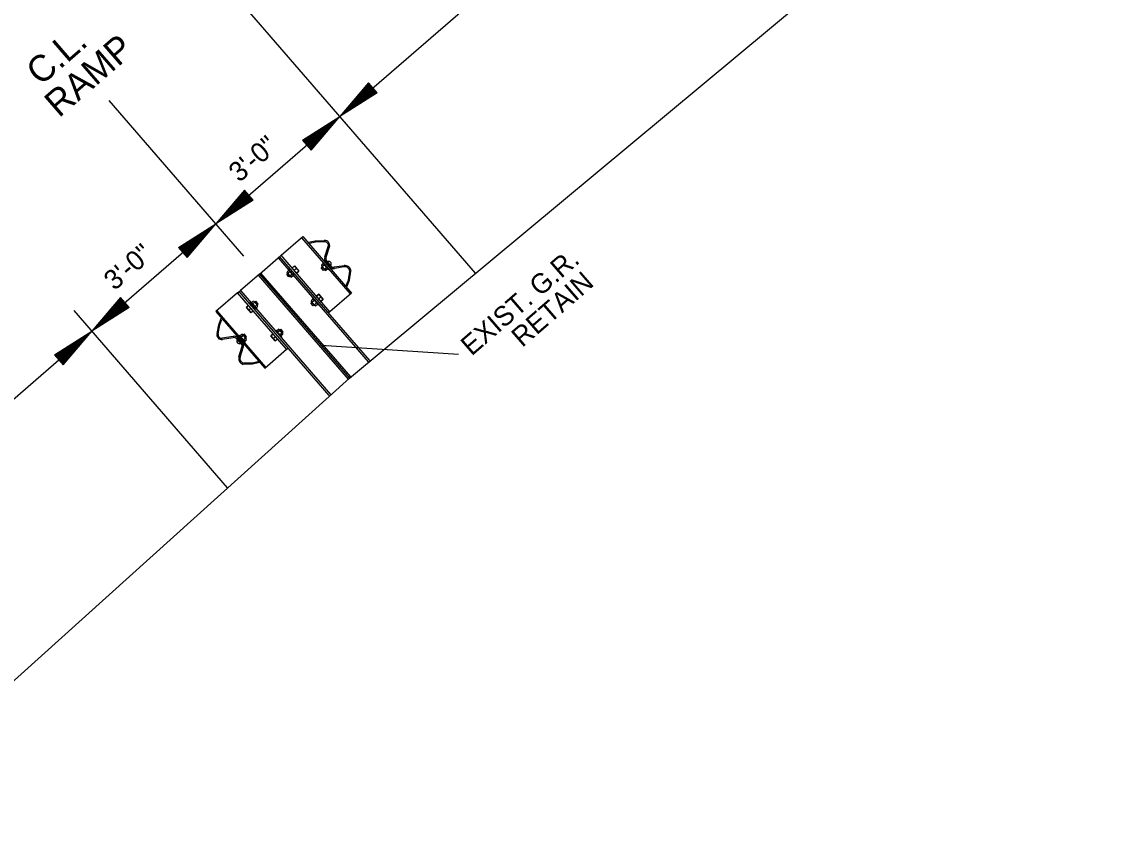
# Model space of a CAD drawing. Extents: x 192699 to 285914, y 194342 to 233219.
# Drawn here: x 262811.72 to 262831.55, y 213663.47 to 213678.17 of the extents above; entities that cross this region are included whole.
import ezdxf

# ---------------------------------------------------------------- set-up
doc = ezdxf.new("R2010")
doc.units = 0
doc.layers.add('TYPICAL SECTION FOR MOT', color=7, linetype='Continuous')

msp = doc.modelspace()

# ---------------------------------------------------------------- linework, layer by layer
at = {"layer": 'TYPICAL SECTION FOR MOT'}
for p, q in [((262817.536, 213676.438), (262828.877, 213686.255)), ((262817.71, 213671.653), (262831.555, 213683.162)), ((262820.018, 213673.571), (262815.245, 213679.084)), ((262818.062, 213677.052), (262817.536, 213676.438)), ((262818.22, 213676.87), (262818.062, 213677.052)), ((262818.22, 213676.87), (262817.536, 213676.438)), ((262818.076, 213677.037), (262817.637, 213676.525)), ((262818.206, 213676.886), (262817.637, 213676.525)), ((262818.089, 213677.021), (262817.741, 213676.615)), ((262818.193, 213676.901), (262817.741, 213676.615)), ((262818.102, 213677.006), (262817.842, 213676.702)), ((262818.18, 213676.916), (262817.842, 213676.702)), ((262818.115, 213676.991), (262817.944, 213676.791)), ((262818.166, 213676.932), (262817.944, 213676.791)), ((262818.129, 213676.975), (262818.045, 213676.878)), ((262818.153, 213676.947), (262818.045, 213676.878)), ((262815.78, 213673.883), (262813.318, 213676.727)), ((262815.268, 213674.474), (262817.536, 213676.438)), ((262816.853, 213676.005), (262817.536, 213676.438)), ((262816.866, 213675.99), (262817.435, 213676.35)), ((262816.879, 213675.974), (262817.331, 213676.26)), ((262816.983, 213675.854), (262817.331, 213676.26)), ((262816.997, 213675.838), (262817.435, 213676.35)), ((262817.01, 213675.823), (262817.536, 213676.438)), ((262816.892, 213675.959), (262817.23, 213676.173)), ((262816.906, 213675.943), (262817.128, 213676.084)), ((262816.957, 213675.884), (262817.128, 213676.084)), ((262816.97, 213675.869), (262817.23, 213676.173)), ((262816.853, 213676.005), (262817.01, 213675.823)), ((262816.919, 213675.928), (262817.027, 213675.997)), ((262816.944, 213675.9), (262817.027, 213675.997)), ((262815.794, 213675.088), (262815.268, 213674.474)), ((262815.807, 213675.073), (262815.369, 213674.561)), ((262815.821, 213675.058), (262815.473, 213674.652)), ((262815.951, 213674.907), (262815.794, 213675.088)), ((262815.951, 213674.907), (262815.268, 213674.474)), ((262815.938, 213674.922), (262815.369, 213674.561)), ((262815.925, 213674.937), (262815.473, 213674.652)), ((262815.834, 213675.043), (262815.574, 213674.739)), ((262815.912, 213674.953), (262815.574, 213674.739)), ((262815.847, 213675.027), (262815.676, 213674.827)), ((262815.898, 213674.968), (262815.676, 213674.827)), ((262815.861, 213675.012), (262815.777, 213674.915)), ((262815.885, 213674.983), (262815.777, 213674.915)), ((262813, 213672.51), (262815.268, 213674.474)), ((262814.585, 213674.041), (262815.268, 213674.474)), ((262814.742, 213673.86), (262815.268, 213674.474)), ((262814.598, 213674.026), (262815.167, 213674.387)), ((262814.611, 213674.011), (262815.063, 213674.297)), ((262814.715, 213673.89), (262815.063, 213674.297)), ((262814.729, 213673.875), (262815.167, 213674.387)), ((262814.624, 213673.995), (262814.962, 213674.209)), ((262814.638, 213673.98), (262814.86, 213674.121)), ((262814.689, 213673.921), (262814.86, 213674.121)), ((262814.702, 213673.905), (262814.962, 213674.209)), ((262817.732, 213673.192), (262816.842, 213674.22)), ((262817.087, 213674.157), (262816.963, 213674.129)), ((262817.088, 213674.137), (262816.985, 213674.114)), ((262817.253, 213674.164), (262817.087, 213674.157)), ((262817.254, 213674.143), (262817.088, 213674.137)), ((262814.585, 213674.041), (262814.742, 213673.86)), ((262814.651, 213673.965), (262814.759, 213674.033)), ((262814.675, 213673.936), (262814.759, 213674.033)), ((262816.46, 213673.9), (262816.409, 213673.852)), ((262818.082, 213671.974), (262816.434, 213673.877)), ((262816.46, 213673.9), (262816.455, 213673.896)), ((262817.261, 213673.868), (262817.322, 213674.06)), ((262817.284, 213673.861), (262817.345, 213674.053)), ((262816.666, 213673.671), (262816.704, 213673.703)), ((262816.704, 213673.703), (262816.785, 213673.609)), ((262817.235, 213673.746), (262817.199, 213673.715)), ((262817.266, 213673.627), (262817.204, 213673.699)), ((262817.256, 213673.723), (262817.219, 213673.691)), ((262817.317, 213673.652), (262817.235, 213673.746)), ((262817.298, 213673.674), (262817.261, 213673.642)), ((262817.298, 213673.674), (262817.265, 213673.646)), ((262817.356, 213673.686), (262817.272, 213673.787)), ((262817.375, 213673.701), (262817.29, 213673.802)), ((262817.613, 213673.708), (262817.434, 213673.681)), ((262817.617, 213673.685), (262817.437, 213673.657)), ((262816.041, 213673.535), (262817.688, 213671.633)), ((262816.064, 213673.555), (262817.71, 213671.653)), ((262816.064, 213673.555), (262817.71, 213671.653)), ((262816.087, 213673.574), (262817.733, 213671.673)), ((262816.605, 213673.625), (262816.569, 213673.593)), ((262816.635, 213673.506), (262816.573, 213673.577)), ((262816.625, 213673.602), (262816.588, 213673.57)), ((262816.687, 213673.53), (262816.605, 213673.625)), ((262816.667, 213673.554), (262816.629, 213673.522)), ((262816.667, 213673.554), (262816.634, 213673.526)), ((262816.687, 213673.53), (262816.649, 213673.498)), ((262816.744, 213673.655), (262816.702, 213673.619)), ((262816.748, 213673.576), (262816.785, 213673.609)), ((262817.317, 213673.652), (262817.279, 213673.619)), ((262817.693, 213673.445), (262817.717, 213673.61)), ((262817.714, 213673.442), (262817.738, 213673.607)), ((262817.647, 213673.333), (262817.693, 213673.445)), ((262817.666, 213673.324), (262817.714, 213673.442)), ((262813.526, 213673.125), (262813, 213672.51)), ((262813.539, 213673.11), (262813.101, 213672.598)), ((262813.553, 213673.094), (262813.205, 213672.688)), ((262813.566, 213673.079), (262813.306, 213672.775)), ((262813.683, 213672.943), (262813.526, 213673.125)), ((262815.666, 213673.212), (262815.72, 213673.255)), ((262815.666, 213673.212), (262815.67, 213673.216)), ((262817.339, 213671.331), (262815.691, 213673.235)), ((262817.048, 213673.097), (262817.011, 213673.065)), ((262817.069, 213673.074), (262817.031, 213673.041)), ((262817.13, 213673.003), (262817.048, 213673.097)), ((262817.151, 213673.186), (262817.114, 213673.154)), ((262817.192, 213673.138), (262817.149, 213673.101)), ((262817.233, 213673.092), (262817.151, 213673.186)), ((262817.233, 213673.092), (262817.195, 213673.059)), ((262815.481, 213669.644), (262812.673, 213672.888)), ((262813.683, 213672.943), (262813, 213672.51)), ((262813.67, 213672.958), (262813.101, 213672.598)), ((262813.657, 213672.974), (262813.205, 213672.688)), ((262813.644, 213672.989), (262813.306, 213672.775)), ((262813.579, 213673.064), (262813.408, 213672.864)), ((262813.63, 213673.005), (262813.408, 213672.864)), ((262813.592, 213673.048), (262813.509, 213672.951)), ((262813.617, 213673.02), (262813.509, 213672.951)), ((262816.184, 213671.852), (262815.294, 213672.88)), ((262815.862, 213672.975), (262815.825, 213672.943)), ((262815.825, 213672.943), (262815.907, 213672.848)), ((262815.867, 213672.896), (262815.909, 213672.933)), ((262815.945, 213672.881), (262815.907, 213672.848)), ((262815.917, 213673.029), (262815.953, 213673.061)), ((262815.999, 213672.935), (262815.917, 213673.029)), ((262815.937, 213673.007), (262815.974, 213673.039)), ((262816.03, 213672.983), (262815.968, 213673.054)), ((262815.979, 213672.958), (262816.016, 213672.99)), ((262815.979, 213672.958), (262816.011, 213672.986)), ((262815.999, 213672.935), (262816.037, 213672.967)), ((262817.079, 213672.978), (262817.017, 213673.05)), ((262817.111, 213673.026), (262817.073, 213672.993)), ((262817.111, 213673.026), (262817.078, 213672.997)), ((262817.13, 213673.003), (262817.092, 213672.97)), ((262815.321, 213672.628), (262815.366, 213672.747)), ((262815.341, 213672.625), (262815.379, 213672.723)), ((262817.354, 213672.865), (262817.329, 213672.843)), ((262801.659, 213662.693), (262813, 213672.51)), ((262812.316, 213672.078), (262813, 213672.51)), ((262812.474, 213671.896), (262813, 213672.51)), ((262815.291, 213672.465), (262815.321, 213672.628)), ((262815.311, 213672.461), (262815.341, 213672.625)), ((262816.376, 213672.515), (262816.413, 213672.547)), ((262816.457, 213672.42), (262816.376, 213672.515)), ((262816.396, 213672.491), (262816.434, 213672.524)), ((262816.489, 213672.468), (262816.427, 213672.539)), ((262812.33, 213672.062), (262812.899, 213672.423)), ((262812.343, 213672.047), (262812.795, 213672.333)), ((262812.447, 213671.927), (262812.795, 213672.333)), ((262812.46, 213671.911), (262812.899, 213672.423)), ((262815.582, 213672.415), (262815.383, 213672.382)), ((262815.586, 213672.391), (262815.387, 213672.358)), ((262815.731, 213672.278), (262815.643, 213672.377)), ((262815.749, 213672.295), (262815.661, 213672.393)), ((262815.707, 213672.423), (262815.743, 213672.454)), ((262815.789, 213672.328), (262815.707, 213672.423)), ((262815.727, 213672.399), (262815.764, 213672.431)), ((262815.82, 213672.375), (262815.758, 213672.447)), ((262815.769, 213672.351), (262815.806, 213672.383)), ((262815.769, 213672.351), (262815.801, 213672.379)), ((262815.789, 213672.328), (262815.826, 213672.361)), ((262816.273, 213672.426), (262816.31, 213672.458)), ((262816.355, 213672.331), (262816.273, 213672.426)), ((262816.315, 213672.379), (262816.357, 213672.415)), ((262816.355, 213672.331), (262816.392, 213672.364)), ((262816.438, 213672.443), (262816.476, 213672.476)), ((262816.438, 213672.443), (262816.47, 213672.471)), ((262816.457, 213672.42), (262816.495, 213672.453)), ((262812.356, 213672.032), (262812.694, 213672.246)), ((262812.37, 213672.016), (262812.592, 213672.157)), ((262812.421, 213671.957), (262812.592, 213672.157)), ((262812.434, 213671.942), (262812.694, 213672.246)), ((262815.69, 213672.043), (262815.743, 213672.217)), ((262815.712, 213672.036), (262815.766, 213672.211)), ((262816.562, 213672.179), (262816.588, 213672.201)), ((262819.706, 213672.084), (262817.196, 213672.246)), ((262812.316, 213672.078), (262812.474, 213671.896)), ((262812.383, 213672.001), (262812.491, 213672.07)), ((262812.407, 213671.973), (262812.491, 213672.07)), ((262815.939, 213671.927), (262815.772, 213671.927)), ((262815.939, 213671.905), (262815.772, 213671.905)), ((262816.057, 213671.956), (262815.939, 213671.927)), ((262816.063, 213671.936), (262815.939, 213671.905)), ((262817.71, 213671.653), (262804.337, 213659.599))]:
    msp.add_line(p, q, dxfattribs=at)
for points in [[(262816.857, 213674.243), (262817.751, 213673.208), (262817.354, 213672.865), (262816.46, 213673.9)], [(262816.703, 213673.703), (262816.785, 213673.608), (262816.743, 213673.572), (262816.661, 213673.667)], [(262817.213, 213673.685), (262817.254, 213673.638), (262817.235, 213673.621), (262817.194, 213673.669)], [(262817.222, 213673.76), (262817.332, 213673.633), (262817.339, 213673.64), (262817.229, 213673.767)], [(262816.582, 213673.564), (262816.623, 213673.517), (262816.604, 213673.501), (262816.563, 213673.548)], [(262816.591, 213673.639), (262816.701, 213673.512), (262816.709, 213673.519), (262816.599, 213673.646)], [(262815.269, 213672.868), (262816.165, 213671.835), (262816.562, 213672.179), (262815.666, 213673.212)], [(262817.034, 213673.111), (262817.144, 213672.984), (262817.151, 213672.991), (262817.041, 213673.118)], [(262817.15, 213673.186), (262817.232, 213673.091), (262817.191, 213673.055), (262817.109, 213673.15)], [(262815.826, 213672.944), (262815.908, 213672.849), (262815.949, 213672.885), (262815.867, 213672.98)], [(262815.905, 213673.045), (262816.015, 213672.918), (262816.007, 213672.911), (262815.897, 213673.038)], [(262815.98, 213673.043), (262816.021, 213672.996), (262816.04, 213673.013), (262815.999, 213673.059)], [(262817.025, 213673.036), (262817.066, 213672.988), (262817.047, 213672.972), (262817.006, 213673.02)], [(262816.364, 213672.531), (262816.474, 213672.404), (262816.466, 213672.398), (262816.356, 213672.525)], [(262816.44, 213672.529), (262816.481, 213672.482), (262816.5, 213672.498), (262816.459, 213672.546)], [(262815.694, 213672.438), (262815.804, 213672.311), (262815.797, 213672.305), (262815.687, 213672.432)], [(262815.77, 213672.436), (262815.811, 213672.389), (262815.83, 213672.405), (262815.789, 213672.453)], [(262816.273, 213672.426), (262816.355, 213672.332), (262816.397, 213672.368), (262816.315, 213672.462)]]:
    msp.add_lwpolyline(points, close=True, dxfattribs=at)
for points in [[(262816.064, 213673.555), (262816.409, 213673.852), (262818.054, 213671.95)], [(262816.064, 213673.555), (262815.72, 213673.255), (262817.367, 213671.355)]]:
    msp.add_lwpolyline(points, dxfattribs=at)
for centre, radius, start, end in [((262817.264, 213674.081), 0.0856, 340.1332, 98.8616), ((262817.264, 213674.081), 0.062, 340.1332, 98.8616), ((262817.341, 213673.837), 0.0865, 158.9893, 215.9277), ((262817.221, 213673.713), 0.022, 175.4578, 263.1077), ((262817.305, 213673.723), 0.0922, 200.6256, 241.141), ((262817.341, 213673.837), 0.0622, 158.9893, 215.9277), ((262817.333, 213673.741), 0.0453, 323.8387, 126.953), ((262817.415, 213673.724), 0.0703, 212.6637, 287.7369), ((262817.415, 213673.724), 0.0462, 212.6637, 287.7369), ((262817.632, 213673.601), 0.109, 6.1017, 100.0033), ((262817.632, 213673.601), 0.0854, 6.1017, 100.0033), ((262816.59, 213673.592), 0.022, 175.4578, 263.1077), ((262816.674, 213673.602), 0.0922, 200.6256, 241.141), ((262816.655, 213673.522), 0.025, 181.8167, 257.5067), ((262817.285, 213673.643), 0.025, 181.8167, 257.5067), ((262815.952, 213673.039), 0.022, 358.6589, 86.3088), ((262815.93, 213672.957), 0.0922, 20.6256, 61.141), ((262816.011, 213672.965), 0.025, 4.2599, 79.9499), ((262817.033, 213673.063), 0.022, 175.4578, 263.1077), ((262817.117, 213673.074), 0.0922, 200.6256, 241.141), ((262817.098, 213672.994), 0.025, 181.8167, 257.5067), ((262816.411, 213672.525), 0.022, 358.6589, 86.3088), ((262816.389, 213672.443), 0.0922, 20.6256, 61.141), ((262815.371, 213672.443), 0.0856, 162.905, 281.6334), ((262815.371, 213672.443), 0.062, 162.905, 281.6334), ((262815.601, 213672.331), 0.0865, 45.8389, 102.7773), ((262815.601, 213672.331), 0.0622, 45.8389, 102.7773), ((262815.697, 213672.326), 0.0453, 134.8136, 297.9279), ((262815.742, 213672.432), 0.022, 358.6589, 86.3088), ((262815.703, 213672.241), 0.0703, 334.0297, 49.1029), ((262815.719, 213672.351), 0.0922, 20.6256, 61.141), ((262815.801, 213672.359), 0.025, 4.2599, 79.9499), ((262816.471, 213672.451), 0.025, 4.2599, 79.9499), ((262815.703, 213672.241), 0.0462, 334.0297, 49.1029), ((262815.794, 213672.009), 0.109, 161.7633, 255.6649), ((262815.794, 213672.009), 0.0854, 161.7633, 255.6649)]:
    msp.add_arc(centre, radius, start, end, dxfattribs=at)

# ---------------------------------------------------------------- texts
for s, height, p in [('C.L.', 0.48, (262812.062, 213676.984)), ('RAMP', 0.48, (262812.398, 213676.401)), ('3\'-0"', 0.36, (262815.697, 213675.217)), ('3\'-0"', 0.36, (262813.414, 213673.24)), ('EXIST. G.R.', 0.36, (262819.944, 213672.045)), ('RETAIN', 0.36, (262820.871, 213672.202))]:
    msp.add_text(s, height=height, rotation=40.8833, dxfattribs=at).set_placement(p)

doc.saveas('drawing.dxf')
